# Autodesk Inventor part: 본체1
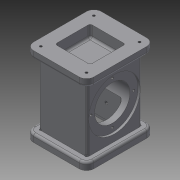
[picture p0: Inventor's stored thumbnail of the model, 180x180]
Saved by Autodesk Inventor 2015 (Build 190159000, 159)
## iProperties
Created: 2017-08
Part Number: 본체1
Material: 일반
Document SubType Name: Modeling
Designer: owner
Density: 1 g/cm^3
Appearance: 기본값
Author: owner
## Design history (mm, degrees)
sketch "스케치1"
  geometry: L1 (33, -37)-(-33, -37); L2 (-33, -37)-(-33, 37); L3 (-33, 37)-(33, 37); L4 (33, 37)-(33, -37); L5 (33, -37)-(-33, 37); L6 (-33, -37)-(33, 37); 1 further point
  constraints: 12 end point, 2 midpoint, 2 parallel, 1 horizontal, 1 perpendicular
  dimensions: "d0" = 66 distance of L2.end L3.end; "d1" = 74 distance of L3.end L1.start
extrude "돌출1" new body sketch "스케치1" stored distance "d2" = 108; taper "d3" = 0 deg
sketch "스케치2"
  geometry: L1 (-26, 26)-(26, 26); L2 (26, 26)-(26, -26); L3 (26, -26)-(-26, -26); L4 (-26, -26)-(-26, 26); L5 (-26, 26)-(26, -26); L6 (26, 26)-(-26, -26); 1 further point
  constraints: 12 end point, 2 midpoint, 2 parallel, 1 horizontal, 1 perpendicular
  dimensions: "d4" = 52 distance of L2.end L3.end; "d5" = 52 distance of L3.end L1.start
extrude "돌출2" cut sketch "스케치2" distance "d6" = 8; taper "d7" = 0 deg
sketch "스케치4"
  geometry: L1 (24, 24)-(-24, 24); L2 (-24, 24)-(-24, -24); L3 (-24, -24)-(24, -24); L4 (24, -24)-(24, 24); L5 (24, 24)-(-24, -24); L6 (-24, 24)-(24, -24); 1 further point
  constraints: 12 end point, 2 midpoint, 2 parallel, 1 horizontal, 1 perpendicular
  dimensions: "d11" = 48 distance of L1.end L2.end; "d12" = 48 distance of L1.start L1.end
extrude "돌출4" cut sketch "스케치4" distance "d13" = 16; taper "d14" = 0 deg
sketch "스케치5"
  geometry: L1 (-33, -37)-(33, -37) reference; L2 (33, -37)-(33, 37) reference; L3 (33, 37)-(-33, 37) reference; L4 (-33, 37)-(-33, -37) reference; L5 (41, 46)-(-41, 46); L6 (-41, 46)-(-41, -46); L7 (-41, -46)-(41, -46); L8 (41, -46)-(41, 46); L9 (41, 46)-(-41, -46); L10 (-41, 46)-(41, -46); 1 further point
  constraints: 12 end point, 2 midpoint, 2 parallel, 1 horizontal, 1 perpendicular
  dimensions: "d15" = 92 distance of L5.end L6.end; "d16" = 82 distance of L5.start L5.end
extrude "돌출5" join sketch "스케치5" distance "d17" = 10; taper "d18" = 0 deg
sketch "스케치6"
  geometry: C1 r 35 at (54, 37); 1 further point
  constraints: 1 centre point, 1 coincident
  dimensions: "d19" = 70 diameter of C1
extrude "돌출6" cut sketch "스케치6" distance "d20" = 3; taper "d21" = 0 deg
hole "구멍1" diameter "d24" = 48; stored, may be unused: countersink angle "d28" = 90 deg, drill point angle "d30" = 0 deg; dims "d22" = 10, "d23" = 10, "d25" = 6, "d26" = 4, "d27" = 2, "d29" = 8
sketch "스케치7"
  geometry: L1 (-22, 22)-(22, 22); L2 (22, 22)-(22, -22); L3 (22, -22)-(-22, -22); L4 (-22, -22)-(-22, 22); L5 (-22, 22)-(22, -22); L6 (22, 22)-(-22, -22); 1 further point
  constraints: 12 end point, 2 midpoint, 2 parallel, 1 horizontal, 1 perpendicular
  dimensions: "d31" = 44 distance of L1.end L2.end; "d32" = 44 distance of L2.end L3.end
extrude "돌출7" cut sketch "스케치7" distance "d33" = 74; taper "d34" = 0 deg
sketch "스케치8"
  geometry: L1 (-41, 46)-(41, 46); L2 (41, 46)-(41, -46); L3 (41, -46)-(-41, -46); L4 (-41, -46)-(-41, 46); L5 (-41, 46)-(41, -46); L6 (41, 46)-(-41, -46); L7 (-33, -37)-(33, -37) reference; L8 (-33, 37)-(-33, -37) reference; L9 (33, 37)-(-33, 37) reference; L10 (33, -37)-(33, 37) reference; 1 further point
  constraints: 12 end point, 2 midpoint, 2 parallel, 1 horizontal, 1 perpendicular
  dimensions: "d35" = 82 distance of L2.end L3.end; "d36" = 92 distance of L3.end L1.start
extrude "돌출8" join sketch "스케치8" distance "d37" = 10; taper "d38" = 0 deg
sketch "스케치9"
  geometry: 2 further points
  dimensions: "d39" = 31 horizontal distance of point (31, -36) point (0, 0); "d40" = 36 vertical distance of point (0, 0) point (31, -36)
hole "구멍2" sketch "스케치9" at (31, -36) diameter "d41" = 3.242; stored, may be unused: countersink angle "d45" = 90 deg, drill point angle "d47" = 118 deg; dims "d42" = 8, "d43" = 4, "d44" = 2, "d46" = 11.8
fillet "모깎기1" dims "d48" = 10
fillet "모깎기2" dims "d49" = 3
sketch "스케치10"
  geometry: L1 (64, -10)-(2, -10) reference; 3 further points
  constraints: 2 vertical alignment
  dimensions: "d51" = 38 distance from line of point (33, 28) L1; "d52" = 42 distance of point (33, 70) point (33, 28)
hole "구멍3" sketch "스케치10" at (33, 70), (33, 28) diameter "d53" = 4.134; stored, may be unused: countersink angle "d57" = 90 deg, drill point angle "d59" = 118 deg; dims "d54" = 10, "d55" = 4, "d56" = 2, "d58" = 27.7
sketch "스케치11"
  geometry: 2 further points
  constraints: 1 horizontal alignment
  dimensions: "d60" = 29 distance of point (0, 0) point (-29, 0)
hole "구멍4" sketch "스케치11" at (-29, 0) diameter "d61" = 3.242; stored, may be unused: countersink angle "d65" = 90 deg, drill point angle "d67" = 118 deg; dims "d62" = 4, "d63" = 4, "d64" = 2, "d66" = 6
fillet "모깎기3" dims "d71" = 3
fillet "모깎기4" dims "d72" = 3
fillet "모깎기6" dims "d74" = 3
fillet "모깎기7" dims "d75" = 3
chamfer "모따기1" distance "d76" = 1; stored, may be unused: second distance "d77" = 2, angle "d78" = 45 deg
sketch "스케치12"
  geometry: L1 (0, -10)-(7, -10) reference; L2 (0, 72)-(0, 0) reference; 2 further points
  constraints: 1 other
  dimensions: "d85" = 46 distance from line of L1 point (4, 36); "d86" = 4 distance from line of point (4, 36) L2
feature "엠보싱1" sketch "스케치12" dims "d0" = 66, "d1" = 74, "d87" = 0.5, "d88" = 0
fillet "모깎기8" dims "d89" = 3
fillet "모깎기9" dims "d90" = 3
node "솔리드1"
mirror "대칭1"
mirror "대칭2"
mirror "대칭3"
mirror "대칭4"
pattern_circular "원형 패턴1" dims angle "d69" = 360 deg
mirror "대칭5"
